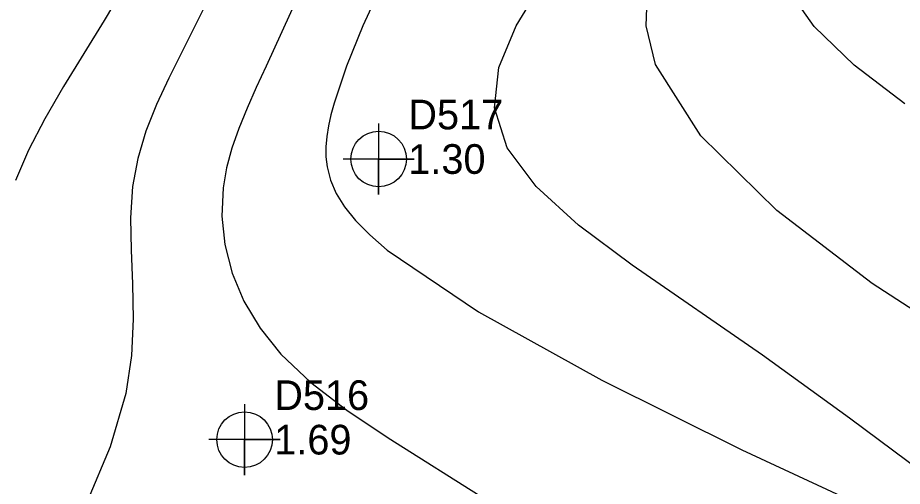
# Model space of a CAD drawing. Extents: x 2356077 to 2359823, y 225951 to 227822.
# Drawn here: x 2357124 to 2357198.6, y 226841 to 226880.5 of the extents above; entities that cross this region are included whole.
import ezdxf

# ---------------------------------------------------------------- set-up
doc = ezdxf.new("R2010")
doc.units = 0
for name, color, linetype in [('DTM Contours Major', 7, 'Continuous'), ('DTM Contours Minor', 7, 'Continuous'), ('Exist DTM Regular Point CELL', 7, 'Continuous'), ('Exist DTM Regular Point Cogo Elevation', 7, 'Continuous'), ('Exist DTM Regular Point Cogo Number', 7, 'Continuous')]:
    doc.layers.add(name, color=color, linetype=linetype)

msp = doc.modelspace()

# ---------------------------------------------------------------- linework, layer by layer
at = {"layer": 'DTM Contours Major'}
msp.add_lwpolyline([(2357132.984, 226883.047), (2357131.322, 226880.248), (2357129.602, 226877.45), (2357127.909, 226874.677), (2357126.329, 226871.954), (2357124.946, 226869.306), (2357123.846, 226866.758)], dxfattribs=at)
at = {"layer": 'DTM Contours Minor'}
for points in [[(2357154.752, 226883.331), (2357153.117, 226879.784), (2357151.741, 226876.38), (2357150.7, 226873.265), (2357150.434, 226872.288), (2357150.223, 226871.356), (2357150.077, 226870.46), (2357150.002, 226869.593), (2357150.007, 226868.75), (2357150.1, 226867.921), (2357150.386, 226866.798), (2357150.871, 226865.676), (2357151.574, 226864.54), (2357152.513, 226863.375), (2357153.707, 226862.167), (2357155.174, 226860.901), (2357162.871, 226855.69), (2357173.252, 226849.93), (2357185.042, 226844.061), (2357196.967, 226838.523)], [(2357201.488, 226841.253), (2357194.117, 226846.743), (2357186.805, 226852.054), (2357175.821, 226859.632), (2357171.302, 226863.006), (2357167.718, 226866.259), (2357165.286, 226869.507), (2357164.22, 226872.865), (2357164.588, 226876.272), (2357166.032, 226879.788), (2357168.163, 226883.309)], [(2357204.748, 226852.432), (2357196.02, 226858.074), (2357188.001, 226864.229), (2357181.61, 226870.512), (2357177.768, 226876.537), (2357176.994, 226879.778), (2357177.108, 226882.815)], [(2357198.785, 226873.22), (2357194.506, 226876.484), (2357191.136, 226879.741), (2357188.922, 226882.904)], [(2357140.24, 226882.318), (2357139.057, 226879.919), (2357137.898, 226877.636), (2357136.775, 226875.389), (2357135.74, 226873.152), (2357134.849, 226870.9), (2357134.155, 226868.606), (2357133.712, 226866.244), (2357133.544, 226863.622), (2357133.587, 226860.89), (2357133.706, 226858.046), (2357133.764, 226855.086), (2357133.624, 226852.009), (2357133.149, 226848.81), (2357131.832, 226844.317), (2357129.892, 226839.715)], [(2357147.612, 226882.192), (2357144.967, 226876.377), (2357144.143, 226874.578), (2357143.37, 226872.843), (2357142.676, 226871.151), (2357142.088, 226869.482), (2357141.633, 226867.815), (2357141.34, 226866.129), (2357141.238, 226863.765), (2357141.495, 226861.365), (2357142.115, 226858.965), (2357143.103, 226856.602), (2357144.463, 226854.312), (2357146.202, 226852.133), (2357148.733, 226849.727), (2357151.763, 226847.41), (2357155.263, 226845.069), (2357163.546, 226839.856)]]:
    msp.add_lwpolyline(points, dxfattribs=at)
at = {"layer": 'Exist DTM Regular Point CELL'}
for points in [[(2357154.451, 226871.567), (2357154.451, 226865.567), (2357154.451, 226868.567), (2357157.451, 226868.567), (2357151.451, 226868.567)], [(2357143.156, 226847.926), (2357143.156, 226841.926), (2357143.156, 226844.926), (2357146.156, 226844.926), (2357140.156, 226844.926)]]:
    msp.add_lwpolyline(points, dxfattribs=at)
for centre in [(2357154.451, 226868.567), (2357143.156, 226844.926)]:
    msp.add_circle(centre, 2.344, dxfattribs=at)

# ---------------------------------------------------------------- texts
at = {"layer": 'Exist DTM Regular Point Cogo Elevation'}
for s, p in [('1.30', (2357156.951, 226867.317)), ('1.69', (2357145.656, 226843.676))]:
    msp.add_text(s, height=2.5, dxfattribs=at).set_placement(p)
at = {"layer": 'Exist DTM Regular Point Cogo Number'}
for s, p in [('D517', (2357156.951, 226871.067)), ('D516', (2357145.656, 226847.426))]:
    msp.add_text(s, height=2.5, dxfattribs=at).set_placement(p)

doc.saveas('drawing.dxf')
